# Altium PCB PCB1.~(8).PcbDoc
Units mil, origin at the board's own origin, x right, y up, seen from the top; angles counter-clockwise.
Board outline 2228.35 x 2228.35 mil, 2 copper layers (Top Layer, Bottom Layer); 17 components, 12 nets, 58 pads, 0 vias.
Unrouted connection lines stored in the file: 37.
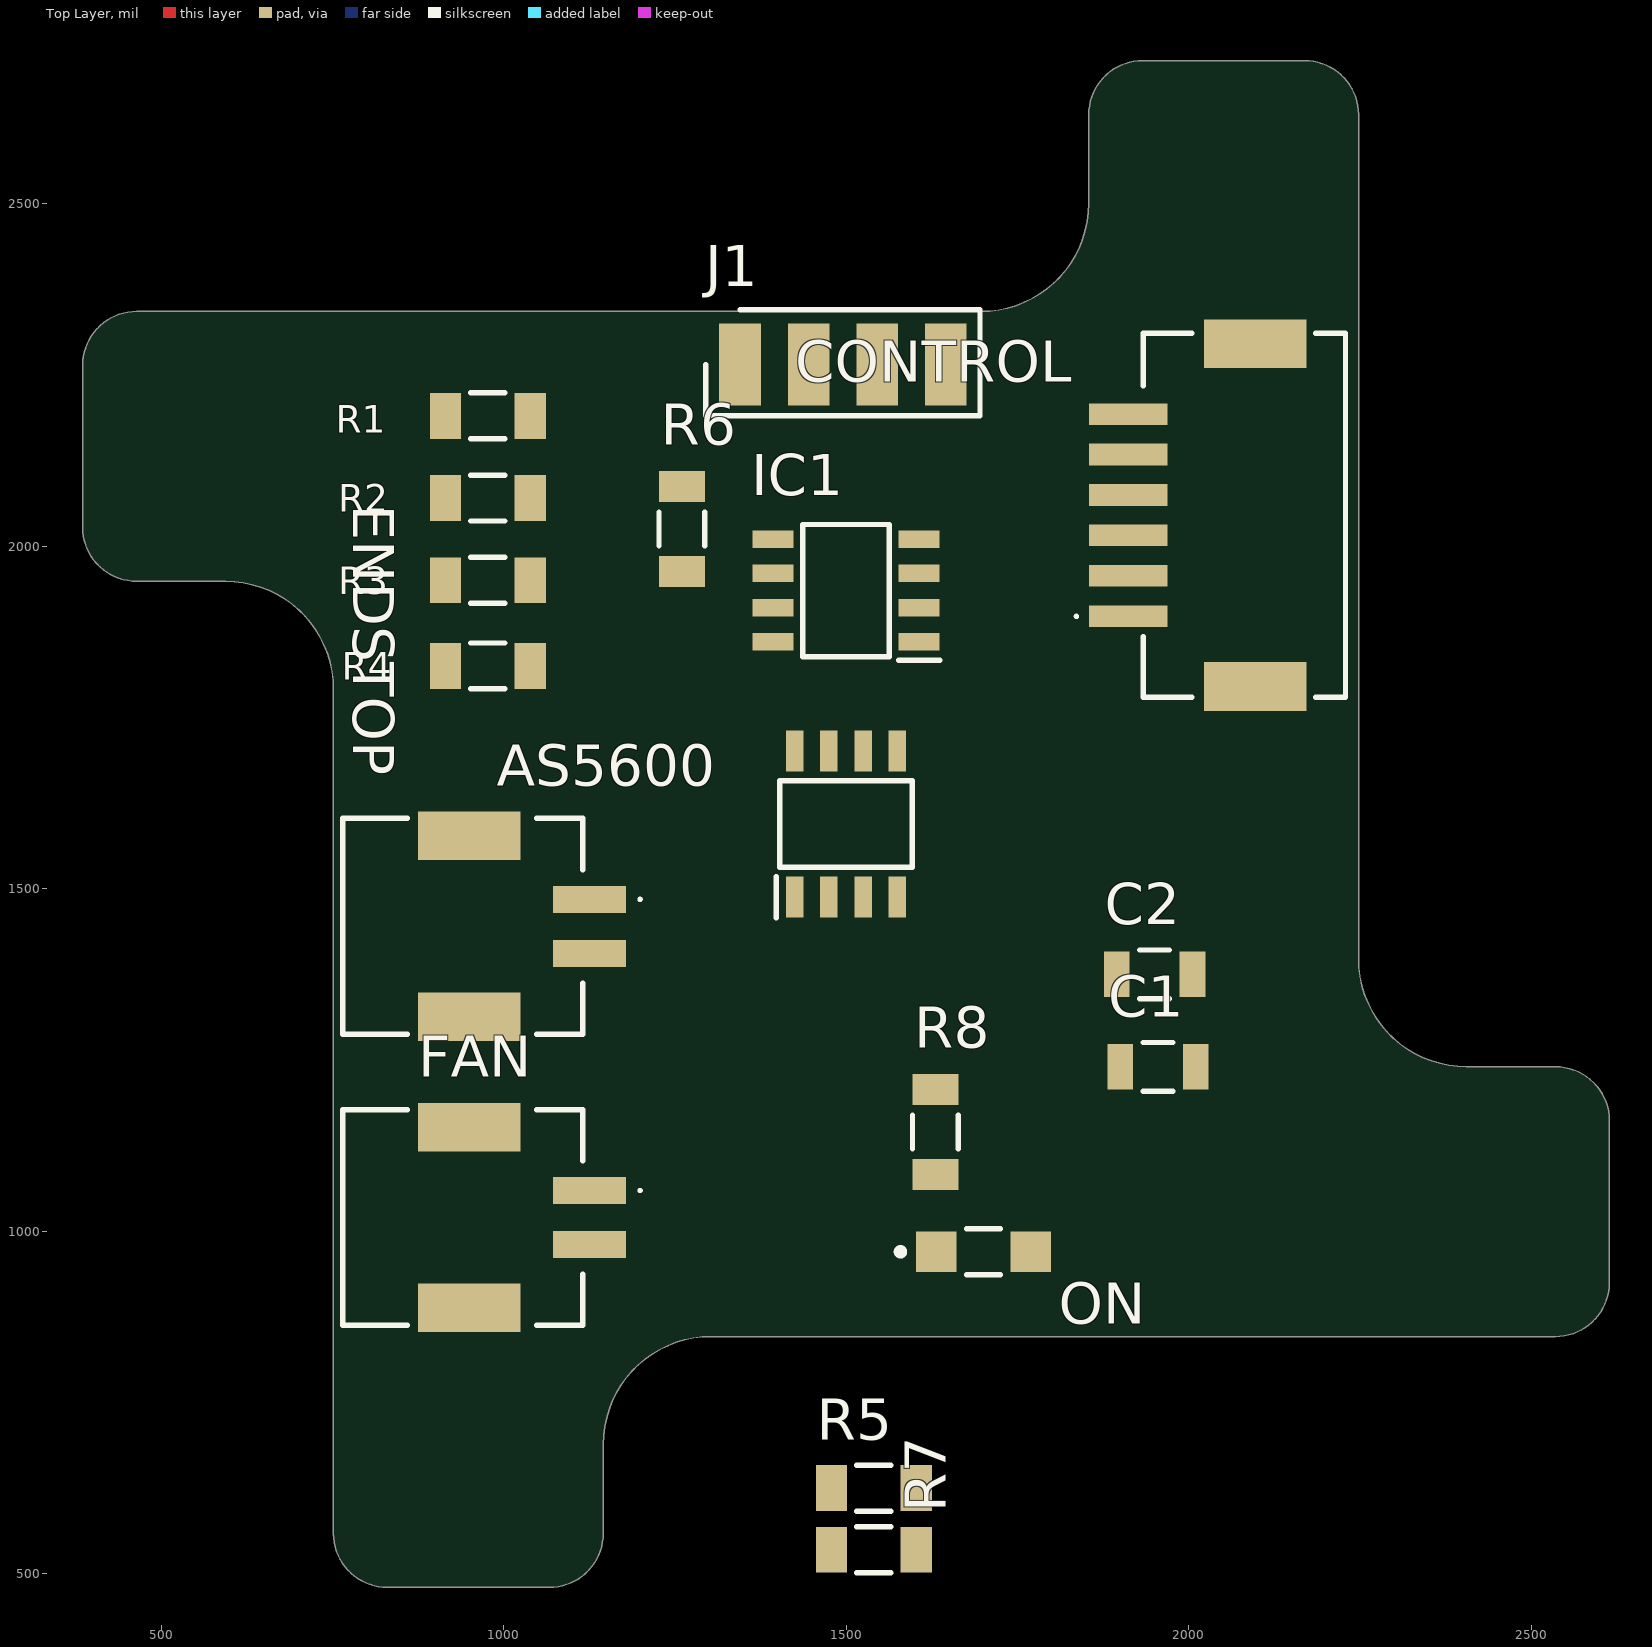
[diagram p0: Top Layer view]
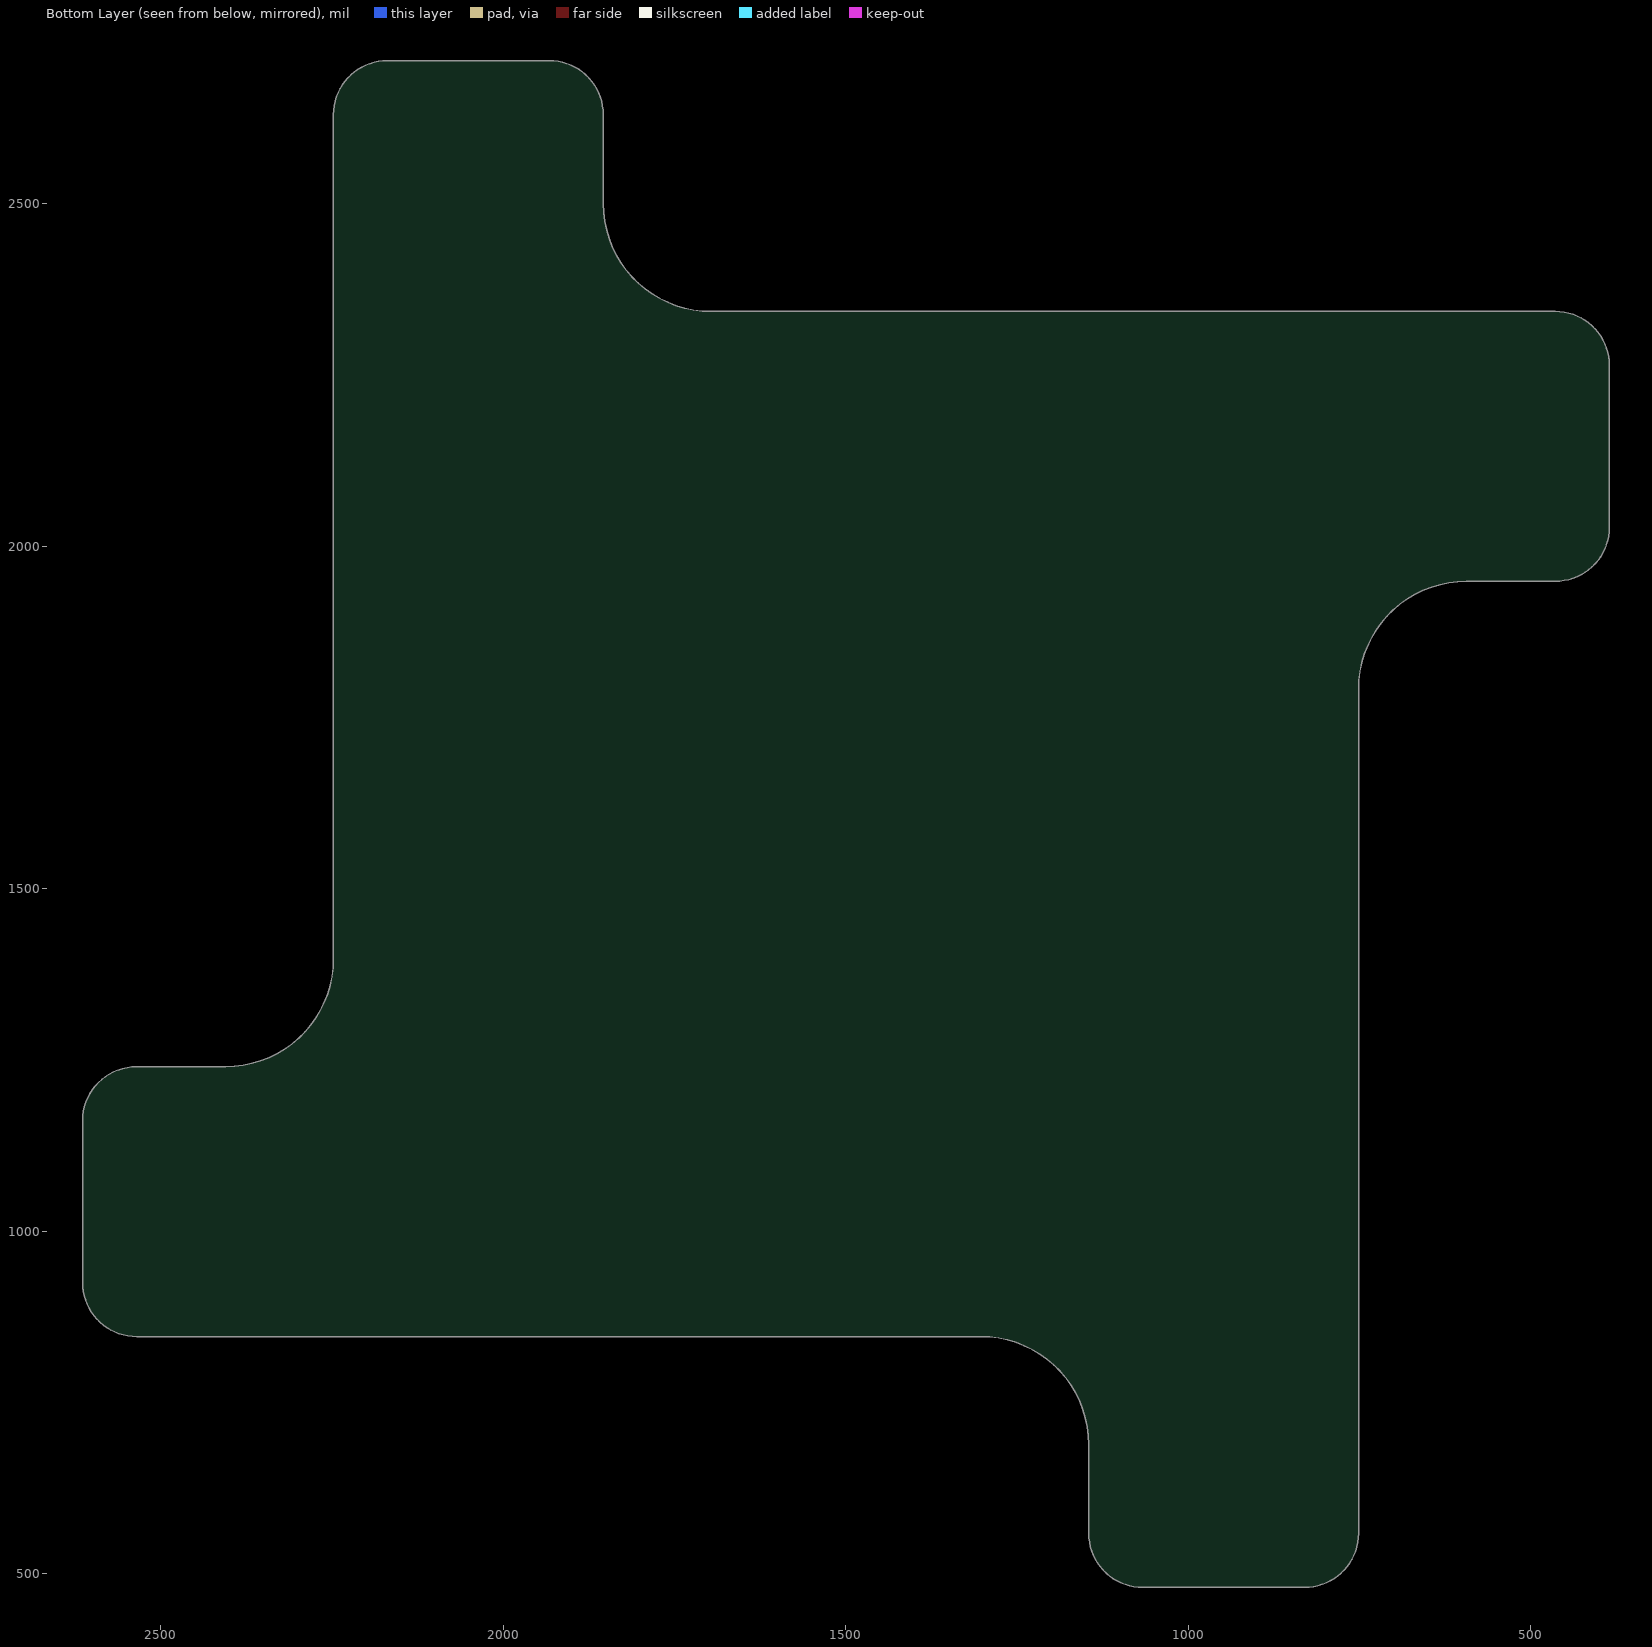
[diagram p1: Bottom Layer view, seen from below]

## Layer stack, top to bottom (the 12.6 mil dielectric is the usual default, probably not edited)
Top Solder: solder mask 0.4, Solder Resist, Dk 3.5
Top Layer: signal copper 1.4
Dielectric 1: dielectric 12.6, FR-4, Dk 4.8
Bottom Layer: signal copper 1.4
Bottom Solder: solder mask 0.4, Solder Resist, Dk 3.5

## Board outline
751.46,558.9 ccw(c830.2,558.9) 830.2,480.16 1066.42,480.16 ccw(c1066.42,558.9) 1145.16,558.9 1145.16,688.82 cw(c1302.64,688.82) 1302.64,846.3 2534.92,846.3 ccw(c2534.92,925.04) 2613.66,925.04 2613.66,1161.26 ccw(c2534.92,1161.26) 2534.92,1240 2405,1240 cw(c2405,1397.48) 2247.52,1397.48 2247.52,2629.76 ccw(c2168.78,2629.76) 2168.78,2708.5 1932.56,2708.5 ccw(c1932.56,2629.76) 1853.82,2629.76 1853.82,2499.84 cw(c1696.34,2499.84) 1696.34,2342.36 464.06,2342.36 ccw(c464.06,2263.62) 385.31,2263.62 385.31,2027.4 ccw(c464.06,2027.4) 464.06,1948.66 593.98,1948.66 cw(c593.98,1791.18) 751.46,1791.18

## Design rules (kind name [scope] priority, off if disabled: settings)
Clearance [All] p1: gap=15.75 ignorepadtopadclearanceinfootprint=FALSE
PolygonConnect [All] p1: connectstyle=Relief reliefconductorwidth=10 reliefentries=4 polygonreliefangle="90 Angle" airgapwidth=10
RoutingVias [All] p1: holewidth=28 width=50 viastyle="Through Hole" minholewidth=28 minwidth=50 maxholewidth=28 maxwidth=50
SolderMaskExpansion [All] p1: expansion=4 istentingtop=FALSE
SupplyNets "Schematic Supply Nets_2" [InNet('+5')] p1: voltage=0.000
SupplyNets "Schematic Supply Nets_1" [InNet('+3.3')] p2: voltage=0.000
SupplyNets "Schematic Supply Nets" [InNet('GND')] p3: voltage=0.000
Width [All] p1: maxlimit=25 minlimit=25 preferedwidth=25
30 further rules are at their usual default settings.

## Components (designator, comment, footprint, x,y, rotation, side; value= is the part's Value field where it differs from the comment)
AS5600 "AS5600-ASOM" SOIC127P600X175-8N 1499.49,1594.33 r90 top
C1 "C1206C102K5HACAUTO" FP-C1206C-EB-MFG 1955,1240 r0 top value="1,000 pF"
C2 "C1206C102K5HACAUTO" FP-C1206C-EB-MFG 1950,1375 r0 top value="1,000 pF"
CONTROL "C" SM06BZESSTBLFSN 2070,2045 r270 top
ENDSTOP "SM02B-PASS-TBT__LF__SN_" SM02BPASSTBTLFSN 945,1445 r90 top
FAN "SM02B-PASS-TBT__LF__SN_" SM02BPASSTBTLFSN 945,1020 r90 top
IC1 "ATTINY412-SSF" SOIC127P600X175-8N 1499.49,1935 r180 top
J1 "MTSW-104-07-G-S-000" HDRV4W64P0X254_1X4_1016X254X864P 1345,2265 r180 top
ON "LTST-C150AKT" FP-LTST-C150AKT-MFG 1700,970 r0 top
R1 "CSR1206FT33L0" FP-CSR1206-MFG 976.66,2190 r180 top
R2 "CSR1206FT33L0" FP-CSR1206-MFG 976.66,2070 r180 top
R3 "CSR1206FT33L0" FP-CSR1206-MFG 976.66,1950 r0 top
R4 "CSR1206FT33L0" FP-CSR1206-MFG 976.66,1825 r0 top
R5 "CSR1206FT33L0" FP-CSR1206-MFG 1540,625 r0 top
R6 "CSR1206FT33L0" FP-CSR1206-MFG 1260,2025 r90 top
R7 "CSR1206FT33L0" FP-CSR1206-MFG 1540,535 r180 top
R8 "CSR1206FT33L0" FP-CSR1206-MFG 1630,1145 r90 top

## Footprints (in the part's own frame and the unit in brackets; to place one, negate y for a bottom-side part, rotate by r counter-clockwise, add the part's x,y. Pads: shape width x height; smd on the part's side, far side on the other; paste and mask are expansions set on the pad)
FP-C1206C-EB-MFG [mm]
  rect 0.95x1.7 smd paste+0 mask+0: 1(-1.4,0) 2(1.4,0)
  silkscreen extent -0.55,-0.9 0.55,0.9, body extent -2,-1 2,1, height 0.25
FP-CSR1206-MFG [mm]
  rect 1.15x1.7 smd paste+0 mask+0: 1(-1.575,0) 2(1.575,0)
  silkscreen extent -0.62,-0.85 0.62,0.85, body extent -2.25,-0.95 2.25,0.95, height 0.25
FP-LTST-C150AKT-MFG [mm]
  rect 1.5x1.5 smd paste+0 mask+0: 1(-1.75,0) 2(1.75,0)
  silkscreen extent -3.2,-0.85 0.62,0.85, body extent -2.6,-0.95 2.6,0.95, height 0.25
HDRV4W64P0X254_1X4_1016X254X864P [mil]
  rect 61.02x120 smd: 1(0,0) 2(-100,0) 3(-200,0) 4(-300,0)
  silkscreen extent -350,-80 50,75, body extent -350,-55 50,45, height 10
SM02BPASSTBTLFSN [mm]
  rect 1x2.7 smd: 1(1,-4.575) 2(-1,-4.575)
  rect 1.8x3.8 smd: 3(3.35,-0.125) 4(-3.35,-0.125)
  silkscreen extent -4,-6.5 4,4.57, body extent -4.07,-5.82 4.07,4.57, height 5.8
SM06BZESSTBLFSN [mm]
  rect 0.8x2.9 smd: 1(3.75,-4.025) 2(2.25,-4.025) 3(0.75,-4.025) 4(-0.75,-4.025) 5(-2.25,-4.025) 6(-3.75,-4.025)
  rect 1.8x3.8 smd: 7(6.35,0.675) 8(-6.35,0.675)
  silkscreen extent -6.75,-6 6.75,4.02, body extent -7.07,-5.4 7.07,4.03, height 5.9
SOIC127P600X175-8N [mm]
  rect 1.525x0.65 smd: 1(-2.712,1.905) 2(-2.712,0.635) 3(-2.712,-0.635) 4(-2.712,-1.905) 5(2.712,-1.905) 6(2.712,-0.635) 7(2.712,0.635) 8(2.712,1.905)
  silkscreen extent -3.47,-2.45 1.6,2.58, body extent -3,-2.45 3,2.45, height 1.75

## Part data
AS5600: "Integrated Circuit", Manufacturer_Name="ams OSRAM", Mouser Part Number=985-AS5600-ASOM
C1 C2: library part CMP-03020-003638-1, "C1206 1,000 pF X8R 10.00% 50 V", Capacitance="1,000 pF", Manufacturer=KEMET, Package=C1206C-EB, Temperature="-55°C to +150°C", Temperature Characteristic=X8R, Temperature Coefficient=15%, Temperature Range High=+150°C, Temperature Range Low=-55°C, Tolerance=0.1, Voltage Rating="50 V"
CONTROL: library part SM06B-ZESS-TB_LF__SN_, "Connector", Manufacturer_Name="JST (JAPAN SOLDERLESS TERMINALS)", Manufacturer_Part_Number=SM06B-ZESS-TB(LF)(SN)
ENDSTOP FAN: "Connector", Arrow Part Number="SM02B-PASS-TBT (LF)(SN)", Manufacturer_Name="JST (JAPAN SOLDERLESS TERMINALS)"
IC1: "Integrated Circuit", Manufacturer_Name=Microchip, Mouser Part Number=579-ATTINY412-SSF
J1: "Connector", Manufacturer_Name=SAMTEC
ON: library part CMP-22017-000004-1, "LED AMBER CLEAR SMD", Colour=Amber, Forward Current=30mA, Forward Voltage=2.1V, Manufacturer=Lite-On, Package=0, Power Dissipation=100mW, Reverse Voltage=5V, Temperature="-55°C to +85°C", Temperature Range High=+85°C, Temperature Range Low=-55°C
R1 R2 R3 R4 R5 R6 R7 R8: library part CMP-26527-002831-1, "General Purpose Thick Film Chip Resistor, 1206, 33mΩ, 1%, 0.5W", Case/Package=1206, Max Operating Temperature=155°C, Max Power Dissipation=500mW, Min Operating Temperature=-55°C, Package Quantity=5000, Resistance=33mR, Resistor Type="Thick Film", Temperature Coefficient=100ppm/°C, Tolerance=1%

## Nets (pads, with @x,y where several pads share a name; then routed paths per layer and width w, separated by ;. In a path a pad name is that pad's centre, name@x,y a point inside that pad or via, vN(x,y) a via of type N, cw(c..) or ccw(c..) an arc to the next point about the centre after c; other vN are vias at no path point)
+3.3: AS5600.2 C2.1 R4.2 R7.1 R7.2
+5: AS5600.1 C1.1 CONTROL.5 CONTROL.7 ENDSTOP.1 ENDSTOP.4 IC1.1 J1.2 ON.2 R1.2 R2.2 R4.1 R5.1 R5.2
GND: AS5600.4 C1.2 C2.2 CONTROL.6 FAN.1 IC1.8 J1.1 R3.1 R8.2
NetAS5600_5: AS5600.5 R3.2
NetCONTROL_1: CONTROL.1 ENDSTOP.2
NetCONTROL_2: CONTROL.2 FAN.2
NetIC1_6: IC1.6 R6.1
NetON_1: ON.1 R8.1
SCL: AS5600.7 IC1.5 R1.1
SDA: AS5600.6 IC1.4 R2.1
TX: CONTROL.3 IC1.2 J1.4
UPDI: J1.3 R6.2
pads on no net: AS5600.3 AS5600.8 CONTROL.4 CONTROL.8 ENDSTOP.3 FAN.3 FAN.4 IC1.3 IC1.7

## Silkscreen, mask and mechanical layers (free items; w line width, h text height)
Mechanical 1:
  circle w1: c2495.55,952.6 r62.99
  circle w0.5: c503.43,2236.06 r62.99
  circle w0.5: c857.76,598.27 r62.99
  circle w0.5: c2141.22,2590.39 r62.99
  lines w0.5: 385.31,2027.4 ccw(c464.06,2027.4) 464.06,1948.66 593.98,1948.66 cw(c593.98,1791.18) 751.46,1791.18 751.46,558.9 ccw(c830.2,558.9) 830.2,480.16 1066.42,480.16 ccw(c1066.42,558.9) 1145.16,558.9 1145.16,688.82 cw(c1302.64,688.82) 1302.64,846.3 2534.92,846.3 ccw(c2534.92,925.04) 2613.66,925.04 2613.66,1161.26 ccw(c2534.92,1161.26) 2534.92,1240 2405,1240 cw(c2405,1397.48) 2247.52,1397.48 2247.52,2629.76 ccw(c2168.78,2629.76) 2168.78,2708.5 1932.56,2708.5 ccw(c1932.56,2629.76) 1853.82,2629.76 1853.82,2499.84 cw(c1696.34,2499.84) 1696.34,2342.36 464.06,2342.36 ccw(c464.06,2263.62) 385.31,2263.62 385.32,2027.4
